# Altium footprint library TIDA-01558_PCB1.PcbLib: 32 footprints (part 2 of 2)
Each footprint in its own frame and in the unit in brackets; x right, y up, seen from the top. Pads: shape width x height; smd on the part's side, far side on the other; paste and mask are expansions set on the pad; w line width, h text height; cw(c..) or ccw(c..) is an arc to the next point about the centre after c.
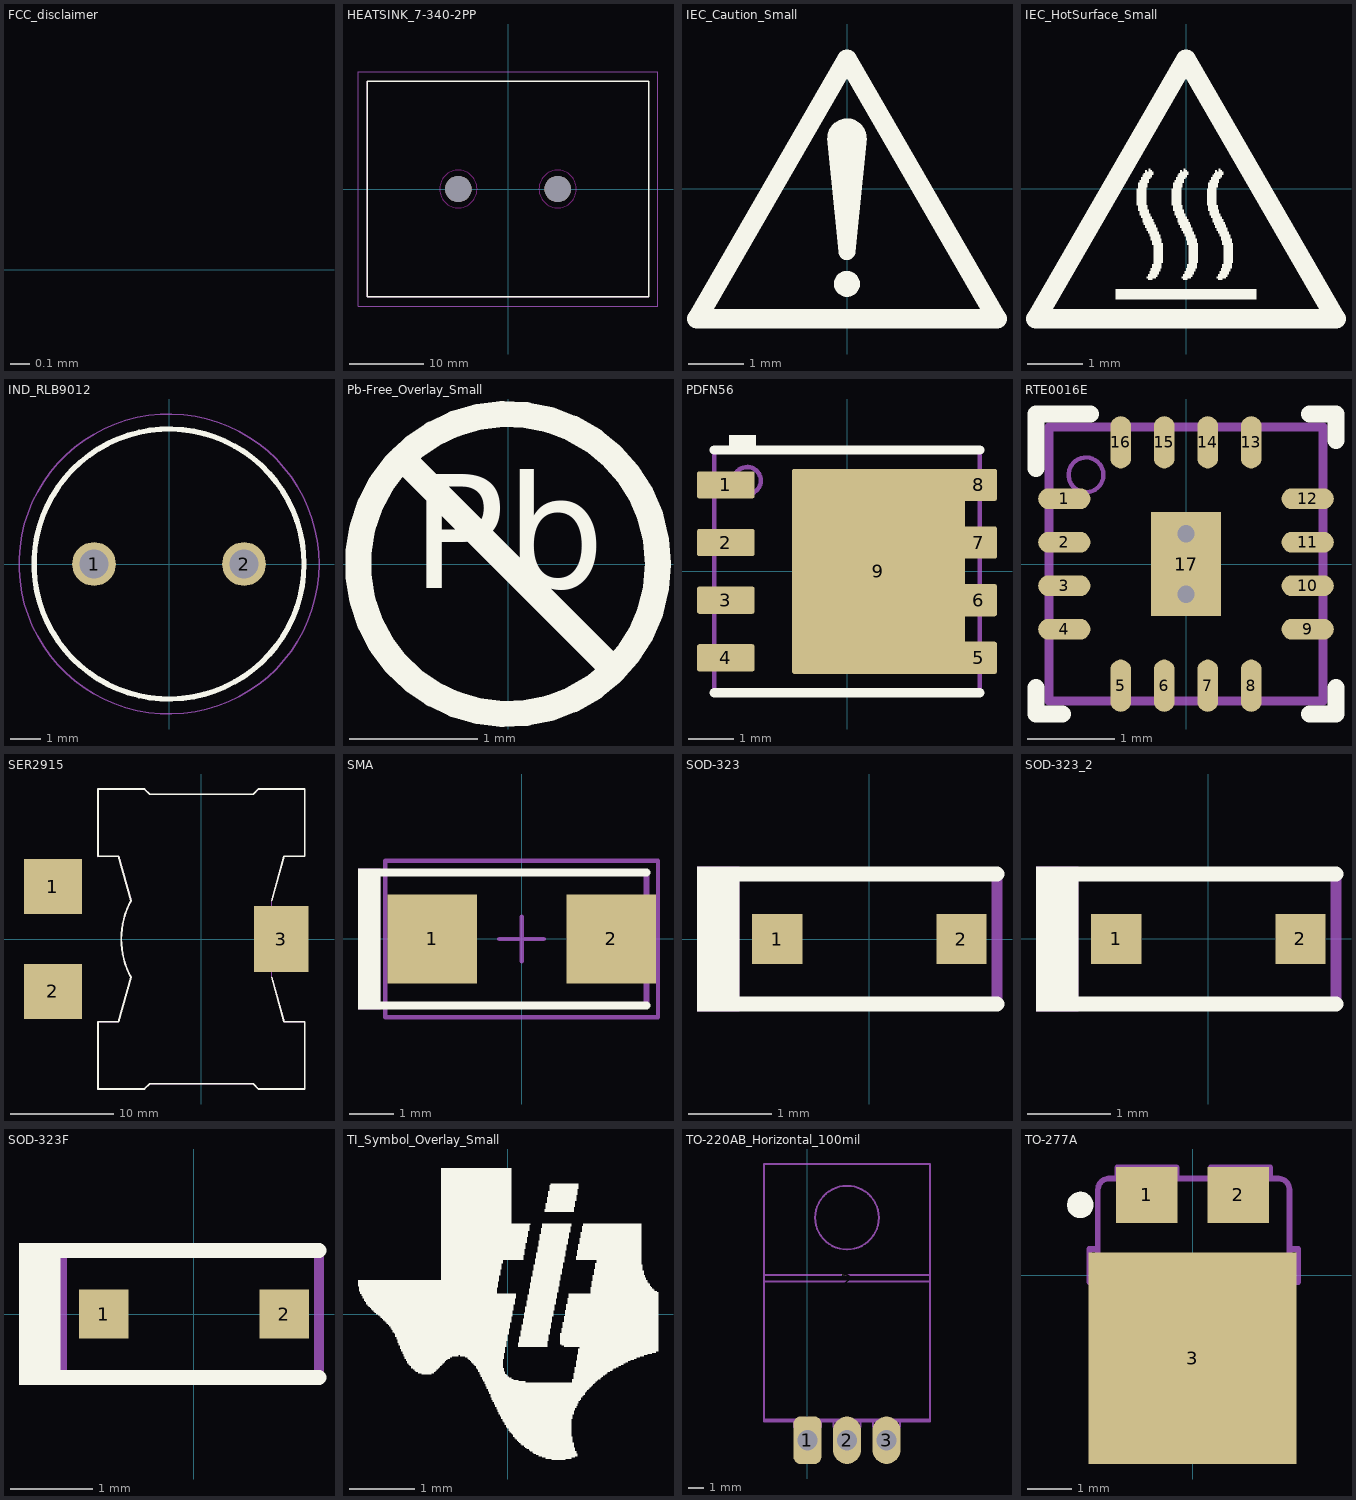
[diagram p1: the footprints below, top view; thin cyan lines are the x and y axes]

## FCC_disclaimer [mm]
Top Overlay:
  text "For evaluation only; not FCC approved for resale." at -15.928,-0.353 h1.52

## HEATSINK_7-340-2PP [mil] "HEATSINK, DUAL TO-220"
height 459.84
pads (2):
  round 140 hole 140 unplated mask+5: ""(-265,0) ""(265,0)
Top Overlay:
  lines w7: -750,-575 750,-575 750,575 -750,575 -750,-575
Bottom Overlay:
  lines w7: -750,-533.93 -750,-575 -708.33,-575 ; -750,-451.79 -750,-369.64 ; -750,-287.5 -750,-205.36 ; -750,-123.21 -750,-41.07 ; -750,41.07 -750,123.21 ; -750,205.36 -750,287.5 ; -625,-575 -541.67,-575 ; -458.33,-575 -375,-575 ; -458.33,575 -375,575 ; -291.67,-575 -208.33,-575 ; -291.67,575 -208.33,575 ; -125,-575 -41.67,-575 ; -125,575 -41.67,575 ; 41.67,-575 125,-575 ; 41.67,575 125,575 ; 208.33,-575 291.67,-575 ; 375,-575 458.33,-575 ; 541.67,-575 625,-575 ; 541.67,575 625,575 ; 708.33,-575 750,-575 750,-533.93 ; 708.33,575 750,575 750,533.93 ; 750,-451.79 750,-369.64 ; 750,-287.5 750,-205.36
Keep-Out Layer:
  circle w1.97: c-265,0 r100
  circle w1.97: c265,0 r100
Mechanical 5:
  lines w5: -750,-575 750,-575 750,575 -750,575 -750,-575
  text ".Designator" at -60,-20 h40
Mechanical 15:
  lines w1.97: -800,-625 800,-625 800,625 -800,625 -800,-625
3D body: height 459.84, standoff 0, extent -750,-575 750,-239
3D body: height 459.84, standoff 0, extent -750,239 750,575
3D body: height 100, standoff 0, extent -750,-239 750,239

## IEC_Caution_Small [mm]
Top Overlay:
  circle w0.254: c0,-1.143 r0.025
  circle w0.356: c0,0.914 r0.178
  circle w0.254: c0,-1.727 r0.108
  region: -0.356,0.914 0.356,0.914 0.152,-1.143 -0.152,-1.143
  lines w0.356: -2.718,-2.362 2.718,-2.362 0,2.345 -2.718,-2.362

## IEC_HotSurface_Small [mm]
Top Overlay:
  drawing of 10 lines, arcs and shapes, not listed

## IND_RLB9012 [mm] "INDUCTOR, RLB9012 SERIES, 2-PIN"
height 12.2
pads (2):
  round 1.462 hole 0.954: 1(-2.5,0) 2(2.5,0)
Top Overlay:
  circle w0.178: c0,0 r4.5
Bottom Overlay:
  lines w0.178: -4.5,0.001 ccw(c0,0) -4.439,-0.74 ; -4.256,-1.461 ccw(c0,0) -3.958,-2.141 ; -3.551,-2.763 ccw(c0,0) -3.048,-3.31 ; -2.462,-3.767 ccw(c0,0) -1.808,-4.121 ; -1.807,4.121 cw(c0,0) -1.104,4.362 ; -1.105,-4.362 ccw(c0,0) -0.372,-4.485 ; 0.371,-4.485 ccw(c0,0) 1.104,-4.362 ; 1.807,-4.121 ccw(c0,0) 2.461,-3.768 ; 3.047,-3.311 ccw(c0,0) 3.551,-2.764 ; 3.958,-2.142 ccw(c0,0) 4.256,-1.461 ; 4.439,-0.741 ccw(c0,0) 4.5,0
Mechanical 5:
  circle w0.127: c0,0 r4.5
  text ".Designator" at -0.61,0.838 h1.02
Mechanical 15:
  circle w0.05: c0,0 r5
Mechanical 17:
  text "MIN. LEAD LENGTH : 13MM" at -10.541,2.159 h1.02
3D body: height 12.2, standoff 0, extent -4.5,-4.5 4.5,4.5

## Pb-Free_Overlay_Small [mm]
Top Overlay:
  circle w0.203: c0,0 r1.168
  lines w0.203: -0.826,0.826 0.826,-0.826
  text "Pb" at -0.752,-0.48 h1.52

## PDFN56 [mm] "SMD, 8-Leads, Body 5.7x5.2mm"
height 1.25
pads (9):
  rrect17% 1.27x0.6 smd: 1(-2.67,1.905) 2(-2.67,0.635) 3(-2.67,-0.635) 4(-2.67,-1.905)
  rrect14% 0.81x0.71 smd: 5(2.9,-1.905) 6(2.9,-0.635) 7(2.9,0.635) 8(2.9,1.905)
  rrect3% 3.81x4.52 smd: 9(0.69,0)
Top Overlay:
  rectangle: -2.6,2.675 -2,3
  lines w0.2: -2.925,-2.675 2.925,-2.675 ; -2.925,2.675 2.925,2.675
Mechanical 5:
  circle w0.1: c-2.2,2 r0.3
  lines w0.1: -2.925,-2.675 2.925,-2.675 2.925,2.675 -2.925,2.675 -2.925,-2.675
  text ".Designator" at 0.025,-0.787 h0.64
3D body: height 1.25, standoff 0, extent -2.925,-2.675 2.925,2.675
3D body: height 1.25, standoff 1.25, extent -2.499,1.701 -1.901,2.299

## RTE0016E [mm] "Texas Insturments"
height 0.8
pads (17):
  oval 0.6x0.24 smd paste+0: 1(-1.4,0.75) 2(-1.4,0.25) 3(-1.4,-0.25) 4(-1.4,-0.75) 9(1.4,-0.75) 10(1.4,-0.25) 11(1.4,0.25) 12(1.4,0.75)
  oval 0.24x0.6 smd paste+0: 5(-0.75,-1.4) 6(-0.25,-1.4) 7(0.25,-1.4) 8(0.75,-1.4) 13(0.75,1.4) 14(0.25,1.4) 15(-0.25,1.4) 16(-0.75,1.4)
  rect 0.8x1.2 smd paste-1: 17(0,0)
via 0,-0.35 diameter 0.5 hole 0.2
via 0,0.35 diameter 0.5 hole 0.2
Top Overlay:
  lines w0.2: -1.725,-1.425 -1.725,-1.725 -1.425,-1.725 ; -1.725,1.1 -1.725,1.725 -1.1,1.725 ; 1.425,-1.725 1.725,-1.725 1.725,-1.425 ; 1.425,1.725 1.725,1.725 1.725,1.425
Top Paste:
  rectangle: -0.379,-0.563 0.389,0.563
Mechanical 5:
  circle w0.05: c-1.15,1.025 r0.2
  lines w0.1: -1.575,-1.575 -1.575,1.575 1.575,1.575 1.575,-1.575 -1.575,-1.575
  text ".Designator" at 0.711,0.374 h0.76
3D body: height 0.8, standoff 0, extent -1.575,-1.575 1.575,1.575
3D body: height 0.81, standoff 0.7, extent -1.349,0.826 -0.951,1.224

## SER2915 [mm] "Coilcraft recommended land pattern.  Document 644-2, rev 12/12/08"
height 15.36
pads (3):
  rect 5.59x5.33 smd: 1(-14.355,5.075) 2(-14.355,-5.075)
  rect 5.28x6.35 smd: 3(7.72,0)
Top Overlay:
  lines w0.178: 6.8,-3.7 8,-8 10,-8 10,-14.5 5.5,-14.5 5,-14 0,-14 -5,-14 -5.5,-14.5 -10,-14.5 -10,-8 -8,-8 -6.8,-3.7 cw(c0,0) -7.741,0 cw(c0,0) -6.8,3.7 -8,8 -10,8 -10,14.5 -5.5,14.5 -5,14 0,14 5,14 5.5,14.5 10,14.5 10,8 8,8 6.8,3.7
Mechanical 5:
  lines w0.102: -6.8,3.675 ccw(c0,-0.025) -7.741,-0.025 ccw(c0,-0.025) -6.8,-3.725 -7.725,-7.05 -7.85,-7.5 -8.025,-8 -10,-8 -10,-14.5 -5.5,-14.5 -5,-14 5,-14 5.5,-14.5 10,-14.5 10,-8 8,-8 6.8,-3.7 6.8,3.675 8.025,8 9.975,8 10,8.025 10,14.5 5.525,14.5 5.025,14 -5,14 -5.475,14.475 -9.975,14.475 -10,7.975 -8,7.975 -6.8,3.725
  text ".Designator" at -0.864,0.635 h1.02
3D body "Coilcraft_SER2915.stp": height 15.36, standoff 0, extent -16.8,-13.95 11.032,13.95

## SMA [mm] "Molded Diode, 2-Leads, Body 4.3x2.6mm, IPC Medium Density, based on OnSemi component dimensions and land pattern"
height 2.27
pads (2):
  rect 2x2 smd: 1(-2,0) 2(2,0)
Top Overlay:
  rectangle: -3.658,-1.575 -3.15,1.575
  lines w0.178: -3.327,-1.486 2.794,-1.486 ; -3.327,1.486 2.794,1.486
Mechanical 5:
  rectangle: -3.658,-1.575 -3.15,1.575
  lines w0.127: -3.327,-1.486 2.794,-1.486 2.794,1.486 -3.327,1.486
  text ".Designator" at -0.914,-0.559 h1.02
Mechanical 15:
  lines w0.1: -0.5,0 0.5,0 ; 0,-0.5 0,0.5 ; -3.05,-1.75 3.05,-1.75 3.05,1.75 -3.05,1.75 -3.05,-1.75
3D body "SMA_nominal.stp": height 2.42, standoff 0.02, extent -2.6,-1.3 2.6,1.3

## SOD-323 [mm] "NXP recommended land pattern"
height 1.15
pads (2):
  rect 0.6x0.6 smd paste-0.05: 1(-1.1,0) 2(1.1,0)
Top Overlay:
  rectangle: -2.057,-0.864 -1.549,0.864
  lines w0.178: -1.803,-0.775 0.1,-0.775 1.525,-0.775 ; -1.803,0.775 0.1,0.775 1.525,0.775
Mechanical 5:
  rectangle: -2.057,-0.864 -1.549,0.864
  lines w0.127: -1.803,-0.775 0.1,-0.775 1.525,-0.775 1.525,0.775 0.1,0.775 -1.803,0.775
  text ".Designator" at 0.66,0.356 h0.76
3D body "SOD-323.stp": height 1.1, standoff 0, extent -1.3,-0.675 1.3,0.675

## SOD-323_2 [mm]
pads (2):
  rect 0.6x0.6 smd paste-0.05: 1(-1.1,0) 2(1.1,0)
Top Overlay:
  rectangle: -2.058,-0.864 -1.55,0.864
  lines w0.178: -1.803,-0.775 0.1,-0.775 1.525,-0.775 ; -1.803,0.775 0.1,0.775 1.525,0.775
Mechanical 5:
  rectangle: -2.058,-0.864 -1.55,0.864
  lines w0.127: -1.803,-0.775 0.1,-0.775 1.525,-0.775 1.525,0.775 0.1,0.775 -1.803,0.775
  text ".Designator" at -0.66,-0.406 h0.76
3D body "SOD-323.stp": height 1.1, standoff 0, extent -1.3,-0.675 1.3,0.675

## SOD-323F [mm] "NXP recommended land pattern"
height 0.8
pads (2):
  rect 0.6x0.6 smd paste-0.05: 1(-1.1,0) 2(1.1,0)
Top Overlay:
  rectangle: -2.134,-0.864 -1.626,0.864
  lines w0.178: -1.803,-0.775 0.1,-0.775 1.525,-0.775 ; -1.803,0.775 0.1,0.775 1.525,0.775
Mechanical 5:
  rectangle: -2.057,-0.864 -1.549,0.864
  lines w0.127: -1.803,-0.775 0.1,-0.775 1.525,-0.775 1.525,0.775 0.1,0.775 -1.803,0.775
  text ".Designator" at -0.787,-0.381 h0.76
3D body "SOD-323F.stp": height 0.79, standoff -0.08, extent -1.35,-0.675 1.35,0.675

## TI_Symbol_Overlay_Small [mm]
Top Overlay:
  drawing of 3 lines, arcs and shapes, not listed

## TO-220AB_Horizontal_100mil [mm] "High Voltage staggered pins"
height 5
pads (4):
  rrect50% 1.8x3.048 hole 1.3: 1(0,4.5)
  oval 1.8x3.048 hole 1.3: 2(2.54,4.5) 3(5.08,4.5)
  rect 11x15 on Mech15: 2(2.54,14.732)
Mechanical 5:
  lines w0.127: -0.865,5.71 -0.865,5.334 -0.505,5.334 -0.505,4.445 0.505,4.445 0.505,5.334 0.865,5.334 0.865,5.71 ; 3.405,5.71 3.405,5.334 3.045,5.334 3.045,4.445 2.035,4.445 2.035,5.334 1.675,5.334 1.675,5.71 ; 4.215,5.71 4.215,5.334 4.575,5.334 4.575,4.445 5.585,4.445 5.585,5.334 5.945,5.334 5.945,5.71 ; -2.795,5.824 7.875,5.824 ; -2.795,5.824 -2.795,14.689 ; -2.795,5.824 -2.795,5.71 1.675,5.71 ; -2.795,14.689 7.875,14.689 ; -2.795,14.689 -2.795,15.11 ; -2.795,15.11 -1.905,15.11 ; -2.795,15.11 -2.795,22.22 7.875,22.22 7.875,15.11 ; -2.795,15.11 -1.905,15.11 ; -1.905,15.11 6.985,15.11 ; 1.675,5.71 7.875,5.71 7.875,5.824 ; 6.985,15.11 7.875,15.11 ; 6.985,15.11 7.875,15.11 ; 7.875,5.824 7.875,14.689 ; 7.875,14.689 7.875,15.11 ; 2.54,16.745 cw(c2.54,18.79) 2.54,20.835 cw(c2.54,18.79) 2.54,16.745
  text ".Designator" at -0.254,10.414 h1.02
3D body "TO-220AB_100mil_TabDown.stp": height 7.8, standoff 0.22, extent -2.795,-2.845 7.875,22.22

## TO-277A [mm] "Vishay"
height 1.2
pads (3):
  rect 1.4x1.27 smd: 1(-1.04,1.83) 2(1.04,1.83)
  rect 4.72x4.8 smd: 3(0,-1.883)
Top Overlay:
  circle w0.3: c-2.55,1.6 r0.15
Mechanical 5:
  lines w0.127: -2.15,-0.15 -2.35,-0.15 -2.35,0.6 -2.15,0.6 ; -1.715,2.2 -1.715,2.45 -0.365,2.45 -0.365,2.2 ; -1.075,-3.95 -1.075,-4.2 1.125,-4.2 1.125,-3.95 ; 0.415,2.2 0.415,2.45 1.765,2.45 1.765,2.2 ; 2.2,-0.15 2.4,-0.15 2.4,0.6 2.2,0.6 ; -2.15,-3.7 ccw(c-1.9,-3.7) -1.9,-3.95 1.95,-3.95 ccw(c1.95,-3.7) 2.2,-3.7 2.2,1.95 ccw(c1.95,1.95) 1.95,2.2 -1.9,2.2 ccw(c-1.9,1.95) -2.15,1.95 -2.15,-3.7
  text ".Designator" at 0.61,-0.254 h1.02
3D body "TO-277A.stp": height 1.2, standoff 0, extent -2.35,-4.2 2.4,2.45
